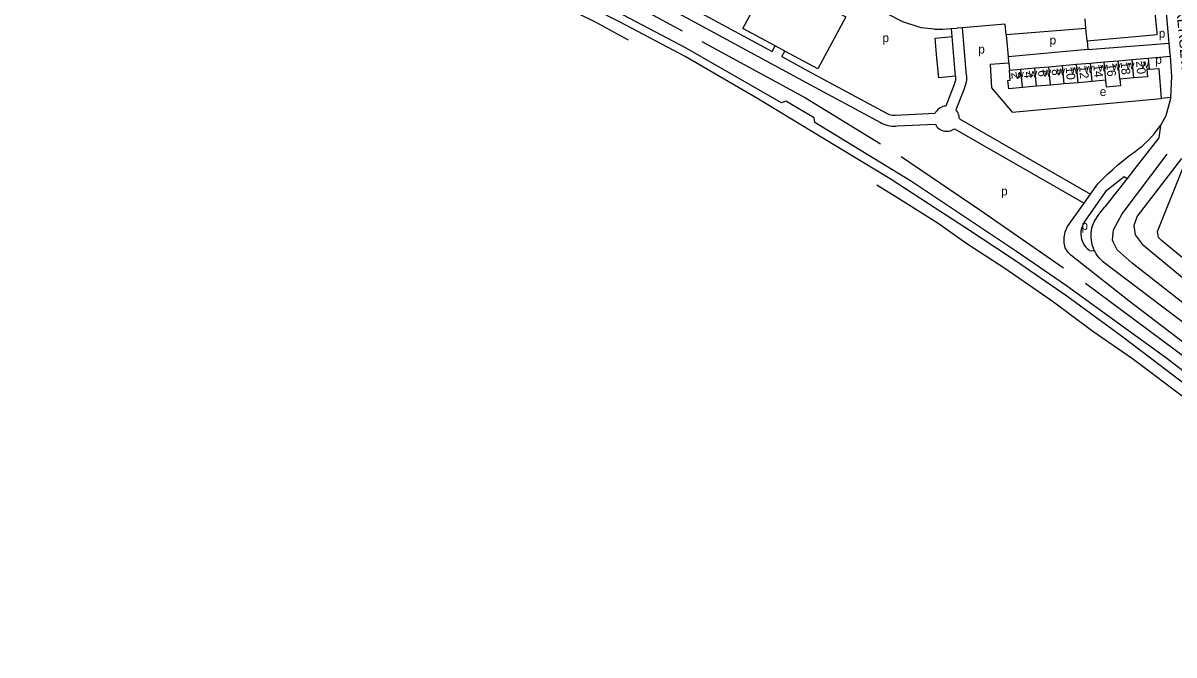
# Model space of a CAD drawing. Extents: x 163026 to 166241, y 382475 to 384501.
# Drawn here: x 163807 to 164331, y 383450 to 383738 of the extents above; entities that cross this region are included whole.
import ezdxf

# ---------------------------------------------------------------- set-up
doc = ezdxf.new("R2010")
doc.units = 0
for name, color, linetype in [('BLT_Basislijn', 7, 'Continuous'), ('BLT_Bebouwing', 7, 'Continuous'), ('BLT_Centroide', 7, 'Continuous'), ('BLT_Huisnummer', 7, 'Continuous'), ('BLT_Huisnummer_ tussenligend', 7, 'Continuous'), ('BLT_Onderverdeling_panden', 7, 'Continuous'), ('BLT_Spoorlijn', 7, 'Continuous'), ('BLT_Straatnaam', 7, 'Continuous')]:
    doc.layers.add(name, color=color, linetype=linetype)

msp = doc.modelspace()

# ---------------------------------------------------------------- linework, layer by layer
at = {"layer": 'BLT_Basislijn'}
for p, q in [((164329.02, 383729.15), (164326.76, 383755.89)), ((164075.75, 383751.78), (164107.18, 383734.72)), ((164101.51, 383750.58), (164148.19, 383725.34)), ((164098.02, 383746.69), (164163.74, 383711.24)), ((164291.13, 383735.79), (164290.81, 383740.21)), ((164229.84, 383735.77), (164232.4, 383735.96)), ((164230.15, 383732.12), (164229.84, 383735.77)), ((164234.83, 383736.16), (164232.4, 383735.96)), ((164236.71, 383714.39), (164234.83, 383736.16)), ((164291.13, 383735.79), (164254.75, 383732.89)), ((164291.67, 383730.22), (164291.13, 383735.79)), ((164230.94, 383723.03), (164230.15, 383732.12)), ((164254.75, 383732.89), (164255.68, 383722.81)), ((164291.67, 383730.22), (164292.04, 383726.23)), ((164292.04, 383726.23), (164329.02, 383729.15)), ((164148.19, 383725.34), (164149.55, 383727.87)), ((164152.58, 383722.96), (164153.96, 383725.49)), ((164292.04, 383726.23), (164255.68, 383722.81)), ((164152.58, 383722.96), (164166.12, 383715.64)), ((164231.72, 383714.03), (164230.94, 383723.03)), ((164255.68, 383722.81), (164255.88, 383720.59)), ((164255.88, 383720.59), (164255.93, 383720.05)), ((164255.93, 383720.05), (164256.22, 383716.85)), ((164319.45, 383722.3), (164329.58, 383723.16)), ((164166.12, 383715.64), (164200.29, 383697.21)), ((164163.74, 383711.24), (164197.52, 383693.04)), ((164231.03, 383710.35), (164227.24, 383700.48)), ((164235.61, 383708.33), (164231.89, 383698.67)), ((164257.53, 383697.75), (164325.35, 383703.88)), ((164329.71, 383704.31), (164325.35, 383703.88)), ((164204.26, 383696.37), (164222.46, 383697.19)), ((164233.45, 383694.64), (164293.24, 383660.38)), ((164205.1, 383691.44), (164222.49, 383692.2)), ((164231.2, 383690.16), (164290.34, 383656.28)), ((164309.86, 383667.54), (164299.73, 383654.5)), ((164290.32, 383647.46), (164300.59, 383662.1)), ((164293.24, 383660.38), (164296.5, 383664.98)), ((164282.75, 383645.55), (164290.34, 383656.28)), ((164290.34, 383656.28), (164293.24, 383660.38)), ((164292.79, 383634.68), (164295.08, 383634.5)), ((164298.69, 383629.84), (164452.06, 383513.21)), ((164290.91, 383619.77), (164359.72, 383568.59))]:
    msp.add_line(p, q, dxfattribs=at)
for points in [[(164487.56, 383450.47), (164485.27, 383453.7), (164461.77, 383475.44), (164415.36, 383515.97), (164364.92, 383557.15), (164327.9, 383585.54), (164282.31, 383618.56), (164259.41, 383634.23), (164211.65, 383666.06), (164167.61, 383692.96), (164167.28, 383695.05), (164154.4, 383702.67), (164152.43, 383702), (164109.02, 383726.87), (164060.25, 383752.65), (163978.72, 383792.41), (163915.23, 383819.71), (163854.36, 383843.93), (163797.39, 383864.74), (163783.25, 383869.74), (163782.14, 383872.57), (163761.29, 383879.43), (163759.17, 383880.76)], [(164222.12, 383735.52), (164216.01, 383736.15), (164207.67, 383738.82), (164161.77, 383762.57), (164153.13, 383765.33), (164148.71, 383766.15), (164142.02, 383766.23), (164098.31, 383762.01)], [(164149.55, 383727.87), (164134.87, 383735.78), (164147.61, 383759.44), (164181.7, 383741.08), (164168.96, 383717.41), (164153.96, 383725.49)], [(164291.67, 383730.22), (164323.52, 383733.09), (164323.56, 383733.92), (164322.59, 383742.85)], [(164222.12, 383735.52), (164225.95, 383735.47), (164229.84, 383735.77)], [(164254.75, 383732.89), (164254.28, 383737.76), (164234.83, 383736.16)], [(164116.18, 383729.84), (164163.38, 383704.21), (164197.58, 383683.22)], [(164231.72, 383714.03), (164224.08, 383713.37), (164223.25, 383722.33), (164222.42, 383731.32), (164230.15, 383732.12)], [(164329.58, 383723.16), (164329.51, 383724.14), (164329.02, 383729.15)], [(164153.96, 383725.49), (164149.55, 383727.87)], [(164255.93, 383720.05), (164247.44, 383719.44), (164248.14, 383708.7), (164257.53, 383697.75)], [(164329.71, 383704.31), (164330.23, 383713.92), (164329.58, 383723.16)], [(164231.72, 383714.03), (164231.72, 383713.29), (164231.64, 383712.48), (164231.49, 383711.69), (164231.25, 383710.91), (164231.03, 383710.35)], [(164236.71, 383714.39), (164236.72, 383713.34), (164236.66, 383712.32), (164236.51, 383711.3), (164236.29, 383710.29), (164235.99, 383709.31), (164235.61, 383708.33)], [(164319.88, 383717.28), (164324.24, 383717.52), (164325.35, 383703.88)], [(164329.71, 383704.31), (164327.44, 383696.01), (164325.1, 383691.55)], [(164227.24, 383700.48), (164226.56, 383700.39), (164225.9, 383700.22), (164225.27, 383699.97), (164224.67, 383699.66), (164224.12, 383699.27), (164223.61, 383698.82), (164223.15, 383698.31), (164222.76, 383697.76), (164222.46, 383697.19)], [(164233.45, 383694.64), (164233.42, 383695.31), (164233.31, 383695.98), (164233.12, 383696.64), (164232.86, 383697.26), (164232.53, 383697.86), (164232.13, 383698.4), (164231.89, 383698.67)], [(164197.52, 383693.04), (164198.31, 383692.57), (164199.14, 383692.17), (164199.99, 383691.84), (164200.88, 383691.59), (164201.78, 383691.41), (164202.69, 383691.31), (164203.61, 383691.3), (164204.52, 383691.36), (164205.1, 383691.44)], [(164200.29, 383697.21), (164200.86, 383696.88), (164201.47, 383696.62), (164202.11, 383696.43), (164202.77, 383696.32), (164203.43, 383696.29), (164204.09, 383696.35), (164204.26, 383696.37)], [(164222.49, 383692.2), (164222.82, 383691.61), (164223.22, 383691.06), (164223.69, 383690.56), (164224.2, 383690.12), (164224.77, 383689.74), (164225.37, 383689.44), (164226.01, 383689.2), (164226.67, 383689.05), (164227.35, 383688.97), (164228.03, 383688.97), (164228.7, 383689.05), (164229.36, 383689.21), (164230, 383689.44), (164230.6, 383689.75), (164231.2, 383690.16)], [(164325.1, 383691.55), (164324.27, 383685.97), (164313.33, 383672.01), (164309.86, 383667.54)], [(164311.83, 383678.54), (164313.48, 383679.71), (164315.09, 383680.93), (164316.65, 383682.23), (164318.16, 383683.58), (164319.61, 383684.99), (164321.01, 383686.46), (164322.35, 383687.98), (164323.62, 383689.56), (164324.84, 383691.18), (164325.1, 383691.55)], [(164206.97, 383677.46), (164242.81, 383653.27), (164280.84, 383626.82)], [(164296.5, 383664.98), (164298.68, 383667.21), (164300.92, 383669.38), (164303.21, 383671.49), (164305.56, 383673.54), (164307.96, 383675.54), (164310.4, 383677.46), (164311.83, 383678.54)], [(164378.11, 383577.24), (164312.18, 383628.95), (164305.35, 383634.92), (164303.85, 383637.95), (164303.28, 383639.45), (164303.59, 383644.07), (164307.63, 383651.37), (164328.14, 383678.48)], [(164334.58, 383676.53), (164314.42, 383650.27), (164312.87, 383646.05), (164313.48, 383641.78), (164316.74, 383637.52), (164399.59, 383569.15)], [(164340.03, 383627.27), (164325.55, 383639.16), (164324.19, 383640.57), (164323.75, 383643.4), (164336.35, 383674.8)], [(164300.59, 383662.1), (164308.46, 383668.36), (164309.86, 383667.54)], [(164294.99, 383648.01), (164296.92, 383651.04), (164299.73, 383654.5)], [(164371.58, 383565.35), (164310.84, 383611.57), (164284.22, 383632.53), (164282.95, 383633.84), (164281.7, 383635.9), (164281.15, 383638.19), (164281.12, 383640.55), (164281.63, 383643.18), (164282.75, 383645.55)], [(164290.32, 383647.46), (164289.88, 383646.73), (164289.51, 383645.95), (164289.21, 383645.14), (164288.98, 383644.31), (164288.84, 383643.46), (164288.77, 383642.6), (164288.79, 383641.74), (164288.88, 383640.89), (164289.05, 383640.04), (164289.3, 383639.22), (164289.63, 383638.42), (164290.03, 383637.66), (164290.49, 383636.93), (164291.03, 383636.26), (164291.62, 383635.63), (164292.27, 383635.07), (164292.79, 383634.68)], [(164295.08, 383634.5), (164294.77, 383635.12), (164294.36, 383636.15), (164294.02, 383637.2), (164293.76, 383638.27), (164293.58, 383639.36), (164293.48, 383640.46), (164293.45, 383641.56), (164293.51, 383642.66), (164293.64, 383643.76), (164293.86, 383644.84), (164294.15, 383645.9), (164294.52, 383646.95), (164294.99, 383648.01)], [(164298.69, 383629.84), (164297.88, 383630.59), (164297.13, 383631.41), (164296.44, 383632.27), (164295.82, 383633.18), (164295.26, 383634.13), (164295.08, 383634.5)]]:
    msp.add_lwpolyline(points, dxfattribs=at)
at = {"layer": 'BLT_Bebouwing'}
for p, q in [((164274.17, 383718.4), (164280.5, 383718.95)), ((164280.5, 383718.95), (164286.82, 383719.49)), ((164286.82, 383719.49), (164293.15, 383720.04)), ((164293.15, 383720.04), (164299.47, 383720.58)), ((164299.47, 383720.58), (164305.8, 383721.13)), ((164305.8, 383721.13), (164312.12, 383721.67)), ((164312.12, 383721.67), (164319.45, 383722.3)), ((164319.45, 383722.3), (164319.88, 383717.28)), ((164256.22, 383716.85), (164261.52, 383717.31)), ((164261.52, 383717.31), (164267.85, 383717.86)), ((164267.85, 383717.86), (164274.17, 383718.4)), ((164312.85, 383713.27), (164306.52, 383712.72)), ((164268.57, 383709.45), (164262.25, 383708.91)), ((164274.9, 383710), (164268.57, 383709.45)), ((164281.22, 383710.54), (164274.9, 383710)), ((164287.55, 383711.09), (164281.22, 383710.54)), ((164293.87, 383711.63), (164287.55, 383711.09)), ((164300.2, 383712.18), (164293.87, 383711.63))]:
    msp.add_line(p, q, dxfattribs=at)
for points in [[(164262.25, 383708.91), (164255.92, 383708.36), (164255.6, 383712.15), (164256.62, 383712.24), (164256.22, 383716.85)], [(164319.88, 383717.28), (164318.88, 383717.19), (164319.17, 383713.81), (164312.85, 383713.27)], [(164306.52, 383712.72), (164306.83, 383709.6), (164300.46, 383709.04), (164300.2, 383712.18)]]:
    msp.add_lwpolyline(points, dxfattribs=at)
at = {"layer": 'BLT_Onderverdeling_panden'}
for p, q in [((164281.22, 383710.54), (164280.5, 383718.95)), ((164287.55, 383711.09), (164286.82, 383719.49)), ((164293.87, 383711.63), (164293.15, 383720.04)), ((164300.2, 383712.18), (164299.47, 383720.58)), ((164306.52, 383712.72), (164305.8, 383721.13)), ((164312.85, 383713.27), (164312.12, 383721.67)), ((164262.25, 383708.91), (164261.52, 383717.31)), ((164268.57, 383709.45), (164267.85, 383717.86)), ((164274.9, 383710), (164274.17, 383718.4))]:
    msp.add_line(p, q, dxfattribs=at)
at = {"layer": 'BLT_Spoorlijn'}
for points in [[(164236.28, 383645.06), (164219.39, 383655.93), (164201.88, 383667.38), (164171.24, 383685.91), (164141.27, 383704.11), (164108.61, 383722.98), (164078.64, 383738.81), (164042.94, 383757.01), (164013.98, 383771.83), (163987.72, 383784.3), (163962.46, 383795.42), (163948.73, 383801.48), (163934.26, 383807.96)], [(164040.87, 383752.01), (164043.68, 383750.6), (164067.59, 383738.81), (164082.6, 383730.6)], [(164195.81, 383664.61), (164204.91, 383658.96), (164223.77, 383647.16), (164236.9, 383637.8)], [(164427.73, 383500), (164408.7, 383516.09), (164382.43, 383537.66), (164340.68, 383570.34), (164307.34, 383595.61), (164282.42, 383613.81), (164258.52, 383630.32), (164236.28, 383645.06)], [(164236.9, 383637.8), (164254.14, 383626.61), (164275.69, 383611.78), (164294.21, 383597.97), (164312.39, 383585.5), (164337.31, 383566.64), (164366.94, 383543.39), (164381.76, 383531.59), (164401.96, 383514.75), (164419.07, 383500)]]:
    msp.add_lwpolyline(points, dxfattribs=at)

# ---------------------------------------------------------------- texts
at = {"layer": 'BLT_Centroide'}
for s, p in [('p', (164324.28, 383731.64)), ('p', (164198.44, 383729.57)), ('p', (164274.56, 383728.53)), ('p', (164242.06, 383724.37)), ('w', (164290.34, 383715.56)), ('w', (164296.67, 383716.11)), ('w', (164303, 383716.64)), ('w', (164309.33, 383717.2)), ('w', (164316, 383717.77)), ('p', (164322.7, 383719.62)), ('w', (164258.92, 383712.86)), ('w', (164265.05, 383713.39)), ('w', (164271.38, 383713.92)), ('w', (164277.7, 383714.48)), ('w', (164284.03, 383715.02)), ('e', (164297.4, 383705.07)), ('p', (164252.47, 383659.77)), ('p', (164289.07, 383644.07))]:
    msp.add_text(s, height=4, dxfattribs=at).set_placement(p)
at = {"layer": 'BLT_Huisnummer'}
for s, rotation, p in [('14', 274.9312, (164294.48, 383719.28)), ('20', 274.9312, (164313.92, 383720.78)), ('2', 274.9175, (164257.08, 383715.62)), ('6', 274.9312, (164269.25, 383716.66)), ('10', 274.9312, (164281.86, 383718.21))]:
    msp.add_text(s, height=4, rotation=rotation, dxfattribs=at).set_placement(p)
at = {"layer": 'BLT_Huisnummer_ tussenligend'}
for s, rotation, p in [('12', 274.9312, (164287.97, 383718.72)), ('16', 274.9312, (164300.39, 383719.69)), ('18', 274.9312, (164306.92, 383720.51)), ('4', 274.9175, (164262.88, 383715.94)), ('8', 274.9312, (164275.47, 383717.17))]:
    msp.add_text(s, height=4, rotation=rotation, dxfattribs=at).set_placement(p)
at = {"layer": 'BLT_Straatnaam'}
msp.add_text('BROEKAKKERSEWEG', height=5, rotation=274.9501, dxfattribs=at).set_placement((164329.52, 383776.79))

doc.saveas('drawing.dxf')
